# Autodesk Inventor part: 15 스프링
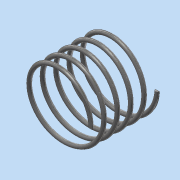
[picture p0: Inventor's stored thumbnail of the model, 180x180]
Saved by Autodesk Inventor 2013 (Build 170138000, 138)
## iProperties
Created: 2016-06
Part Number: 15 스프링
Material: 강철, 탄소
Document SubType Name: Modeling
Designer: Administrator
Density: 7.87 g/cm^3
Mass: 1.62548 g
Surface Area: 8.36348 cm^2
Volume: 0.206541 cm^3
Author: Administrator
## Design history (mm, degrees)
sketch "스케치1"
  geometry: L1 (0, 0)-(8.5, 0); L2 (8.5, 0)-(8.5, 16.67); L3 (8.5, 16.67)-(0, 16.67); L4 (0, 16.67)-(0, 0); C1 r 0.5 at (8.5, 0)
  constraints: 8 end point, 2 parallel, 1 centre point, 1 coincident, 1 horizontal, 1 perpendicular
  dimensions: "d0" = 16.66987 distance of L3.end L1.start (derived); "d1" = 1 diameter of C1; "d2" = 17 diameter of L2 L4
feature "코일1" sketch "스케치1" pitch "d3" = 10; turns "d5" = 5; dims "d4" = 16.66987 (= d0), "d6" = 0, angle "d7" = 90 deg, angle "d8" = 90 deg, "d9" = 0, "d10" = 0
sketch "스케치2"
  geometry: L1 (0, 15)-(16.67, 15); L2 (16.67, 15)-(16.67, -15); L3 (16.67, -15)-(0, -15); L4 (0, -15)-(0, 15); 4 further points
  constraints: 8 end point, 2 coincident, 2 midpoint, 2 parallel, 1 horizontal, 1 perpendicular
  dimensions: "d11" = 30 distance of L1.end L2.end
extrude "돌출1" sketch "스케치2" stored distance "d13" = 50; taper "d14" = 0 deg
node "솔리드1"
